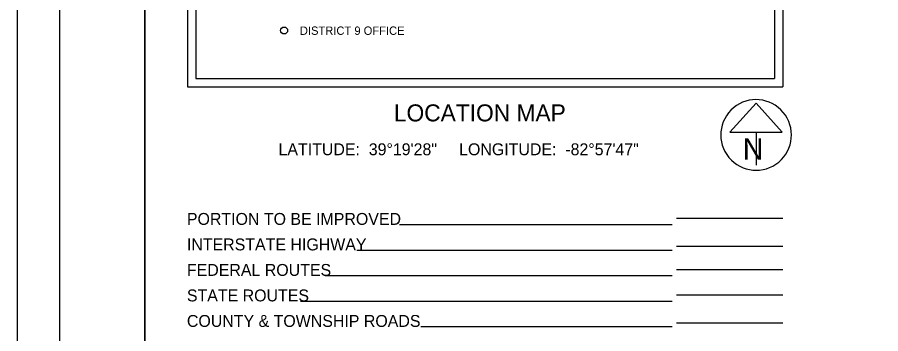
# Model space of a CAD drawing. Extents: x 0 to 40.2, y 0 to 22.
# Drawn here: x 0 to 10.15, y 11.1 to 14.82 of the extents above; entities that cross this region are included whole.
import ezdxf

# ---------------------------------------------------------------- set-up
doc = ezdxf.new("R2010")
doc.units = 0
for name, color, linetype in [('Default', 7, 'Continuous'), ('SH_Border', 7, 'Continuous'), ('SH_Cut_Line', 7, 'Continuous'), ('SH_Data', 7, 'Continuous'), ('SH_Text', 7, 'Continuous')]:
    doc.layers.add(name, color=color, linetype=linetype)

msp = doc.modelspace()

# ---------------------------------------------------------------- linework, layer by layer
at = {"layer": 'Default'}
msp.add_circle((3.137, 14.663), 0.0411, dxfattribs=at)
at = {"layer": 'SH_Border'}
for points in [[(0.5, 21.5), (1.5, 21.5), (1.5, 0.5), (0.5, 0.5)], [(1.5, 21.5), (33.5, 21.5), (33.5, 0.5), (1.5, 0.5)]]:
    msp.add_lwpolyline(points, close=True, dxfattribs=at)
at = {"layer": 'SH_Cut_Line'}
msp.add_lwpolyline([(0, 0), (34, 0), (34, 22), (0, 22)], close=True, dxfattribs=at)
at = {"layer": 'SH_Data'}
for p, q in [((2, 21), (2, 14)), ((9, 21), (9, 14)), ((2.1, 20.9), (2.1, 14.1)), ((8.9, 20.9), (8.9, 14.1)), ((2.1, 14.1), (8.9, 14.1)), ((2.1, 14.1), (2.1, 14.1)), ((2, 14), (9, 14)), ((8.685, 13.809), (8.377, 13.468)), ((8.992, 13.468), (8.685, 13.809)), ((8.377, 13.468), (8.992, 13.468)), ((8.685, 13.468), (8.685, 13.081)), ((8.685, 13.435), (8.685, 13.435)), ((8.685, 13.435), (8.685, 13.435)), ((7.75, 12.455), (9, 12.455)), ((7.7, 12.377), (4.494, 12.377)), ((9, 12.121), (7.75, 12.121)), ((7.7, 12.077), (3.99, 12.077)), ((7.7, 11.777), (3.619, 11.777)), ((9, 11.849), (7.75, 11.849)), ((7.7, 11.477), (3.329, 11.477)), ((9, 11.549), (7.75, 11.549)), ((7.7, 11.177), (4.745, 11.177)), ((9, 11.222), (7.75, 11.222))]:
    msp.add_line(p, q, dxfattribs=at)
msp.add_arc((8.685, 13.435), 0.415, 129.7798, 129.7633, dxfattribs=at)

# ---------------------------------------------------------------- texts
at = {"layer": 'Default'}
msp.add_text('DISTRICT 9 OFFICE', height=0.098, dxfattribs=at).set_placement((3.322, 14.612))
at = {"layer": 'SH_Data'}
msp.add_text('N', height=0.25, dxfattribs=at).set_placement((8.529, 13.144))
at = {"layer": 'SH_Text'}
for s, height, p in [('LOCATION MAP', 0.2, (4.427, 13.594)), ('LATITUDE:  39°19\'28"     LONGITUDE:  -82°57\'47"', 0.14, (3.071, 13.196)), ('PORTION TO BE IMPROVED', 0.14, (1.994, 12.377)), ('INTERSTATE HIGHWAY', 0.14, (1.994, 12.077)), ('FEDERAL ROUTES', 0.14, (1.994, 11.777)), ('STATE ROUTES', 0.14, (1.994, 11.477)), ('COUNTY & TOWNSHIP ROADS', 0.14, (1.994, 11.177))]:
    msp.add_text(s, height=height, dxfattribs=at).set_placement(p)

doc.saveas('drawing.dxf')
